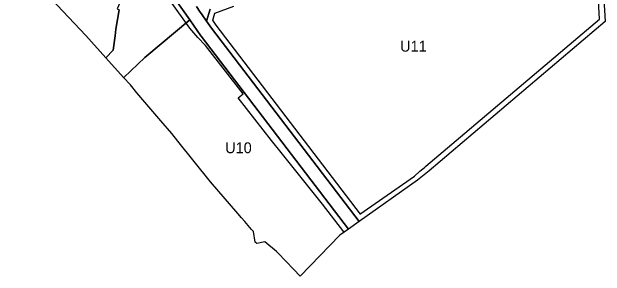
# Model space of a CAD drawing. Extents: x 7425930 to 7427318, y 5544765 to 5546387.
# Drawn here: x 7426551 to 7427100, y 5544765 to 5545009 of the extents above; entities that cross this region are included whole.
import ezdxf

# ---------------------------------------------------------------- set-up
doc = ezdxf.new("R2010")
doc.units = 0
for name, color, linetype in [('linie_rozgraniczajace', 7, 'Continuous'), ('linie_zabudowy_nieprzekraczalne', 7, 'Continuous'), ('oznaczenia_przeznaczen', 7, 'Continuous')]:
    doc.layers.add(name, color=color, linetype=linetype)

msp = doc.modelspace()

# ---------------------------------------------------------------- linework, layer by layer
at = {"layer": 'linie_rozgraniczajace'}
for points in [[(7426550.99, 5545059.69), (7426556.82, 5545058.61), (7426558, 5545058.53), (7426558.08, 5545058.51), (7426580.83, 5545059.17), (7426581.04, 5545059.22), (7426581.23, 5545059.2), (7426596.72, 5545060.69), (7426596.75, 5545060.69), (7426596.9, 5545060.71), (7426628.57, 5545064.71), (7426629.01, 5545050.75), (7426629.17, 5545046.79), (7426664.78, 5545047.04), (7426663.9, 5545029.53), (7426653.18, 5545022.87), (7426648.48, 5545011.56), (7426650.37, 5545010.58), (7426647.24, 5544992.98), (7426646.45, 5544986.59), (7426644.66, 5544973.48), (7426637.91, 5544966.51), (7426619.41, 5544987.05)], [(7426654.38, 5544948.21), (7426654.4, 5544948.25), (7426674.04, 5544966.79), (7426715.65, 5545001.38), (7426725.83, 5544986.66), (7426725.93, 5544986.55), (7426726, 5544986.43), (7426862.25, 5544808.25), (7426862.27, 5544808.23), (7426854.33, 5544802.65), (7426817.63, 5544764.76), (7426811.44, 5544771.25), (7426797.38, 5544785.97), (7426795.64, 5544787.44), (7426784.98, 5544796.41), (7426777.48, 5544794.89), (7426775.93, 5544796.09), (7426774.38, 5544806.01), (7426772.75, 5544807.88), (7426766.33, 5544815.21), (7426763.42, 5544818.53), (7426759.99, 5544822.52), (7426734.83, 5544851.8), (7426704.37, 5544889.53), (7426698.8, 5544896.43), (7426688.64, 5544908.27), (7426685.13, 5544912.37), (7426666.64, 5544933.92), (7426660.57, 5544941.34)]]:
    msp.add_lwpolyline(points, close=True, dxfattribs=at)
for points in [[(7427097.53, 5545036.19), (7427099.73, 5544999.86), (7426936.82, 5544862.15), (7426926.31, 5544853.27), (7426872.09, 5544815.14), (7426872.09, 5544815.14), (7426735.62, 5544993.61), (7426731.07, 5545000.18), (7426734.33, 5545011.24)], [(7426702.14, 5545020.92), (7426715.65, 5545001.38), (7426674.04, 5544966.79), (7426654.4, 5544948.25), (7426654.38, 5544948.21), (7426654.27, 5544948.34), (7426637.91, 5544966.51), (7426644.66, 5544973.48), (7426646.45, 5544986.59), (7426647.24, 5544992.98), (7426650.37, 5545010.58)], [(7426721.67, 5545013.77), (7426725.19, 5545008.68), (7426725.59, 5545008.11), (7426725.59, 5545008.11), (7426726.99, 5545006.08), (7426731.07, 5545000.18), (7426735.62, 5544993.61), (7426872.09, 5544815.14), (7426862.27, 5544808.23), (7426862.25, 5544808.25), (7426726, 5544986.43), (7426725.93, 5544986.55), (7426725.83, 5544986.66), (7426715.65, 5545001.38), (7426702.14, 5545020.92)], [(7426734.33, 5545011.24), (7426731.07, 5545000.18), (7426726.99, 5545006.08), (7426725.59, 5545008.11), (7426725.59, 5545008.11), (7426725.19, 5545008.68), (7426721.67, 5545013.77)]]:
    msp.add_lwpolyline(points, dxfattribs=at)
at = {"layer": 'linie_zabudowy_nieprzekraczalne'}
for points in [[(7426858.11, 5544805.51), (7426838.33, 5544831.26), (7426800.21, 5544878.94), (7426791.21, 5544889.94), (7426760.21, 5544929.31), (7426764.88, 5544933.06), (7426730.1, 5544977.78), (7426723.05, 5544985.09), (7426715.52, 5544993.89), (7426697.67, 5545018.58), (7426687.92, 5545040.29), (7426687.14, 5545043.3), (7426686.1, 5545055.84), (7426685.97, 5545059.25)], [(7426872.98, 5544821.87), (7426923.25, 5544857.22), (7426928.43, 5544861.6), (7426931.02, 5544863.79), (7426932.31, 5544864.89), (7426932.96, 5544865.43), (7426933.29, 5544865.71), (7426933.45, 5544865.84), (7426933.53, 5544865.91), (7426933.57, 5544865.95), (7426933.58, 5544865.96), (7426933.58, 5544865.96), (7426933.59, 5544865.96), (7426933.59, 5544865.97), (7426933.63, 5544866), (7426933.94, 5544866.27), (7427094.58, 5545002.06), (7427092.54, 5545035.88)], [(7426755.86, 5545013.62), (7426738.41, 5545007.38)], [(7426738.41, 5545007.38), (7426736.51, 5545000.92)], [(7426736.54, 5545001.05), (7426739.66, 5544996.54), (7426873.13, 5544821.99)]]:
    msp.add_lwpolyline(points, dxfattribs=at)

# ---------------------------------------------------------------- texts
at = {"layer": 'oznaczenia_przeznaczen'}
for s, p in [('U11', (7426910.12, 5544972.08)), ('U10', (7426748.32, 5544878.3))]:
    msp.add_text(s, height=10, dxfattribs=at).set_placement(p)

doc.saveas('drawing.dxf')
